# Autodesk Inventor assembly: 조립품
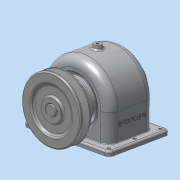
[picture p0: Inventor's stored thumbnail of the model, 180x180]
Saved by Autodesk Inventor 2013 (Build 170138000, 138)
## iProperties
Created: 2015-09
Part Number: 조립품
Document SubType Name: Assembly
Designer: Administrator
Author: Administrator
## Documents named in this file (14)
- C:\Users\Administrator\Desktop\450908V1024\조립품.iam
- C:\Users\Administrator\Desktop\450908V1024\본체.ipt
- C:\Users\Administrator\Desktop\450908V1024\축.ipt
- C:\Users\Administrator\Desktop\450908V1024\앞커버.ipt
- C:\Users\Administrator\Desktop\450908V1024\베어링 6203.ipt
- C:\Users\Administrator\Desktop\450908V1024\오일 실 17 32 8.ipt
- C:\Users\Administrator\Desktop\450908V1024\키 - 5 x 5 x 18.ipt
- C:\Users\Administrator\Desktop\450908V1024\멈춤나사 - M4x10.ipt
- C:\Users\Administrator\Desktop\450908V1024\V-벨트풀리.ipt
- C:\Users\Administrator\Desktop\450908V1024\볼트 M3 x 10.ipt
- C:\Users\Administrator\Desktop\450908V1024\뒤커버.ipt
- C:\Users\Administrator\Desktop\450908V1024\볼트 M3 x 8.ipt
- C:\Users\Administrator\Desktop\450908V1024\키 - 6 x 6 x 22.ipt
- C:\Users\Administrator\Desktop\450908V1024\스퍼기어.ipt
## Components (9 placed, 3 different names)
1. V-벨트풀리:1
2. ISO 4762 M3 x 10:1
3. ISO 4762 M3 x 10:2
4. ISO 4762 M3 x 10:3
5. ISO 4762 M3 x 10:4
6. ISO 4762 M3 x 8:1
7. ISO 4762 M3 x 8:2
8. ISO 4762 M3 x 8:3
9. ISO 4762 M3 x 8:4
